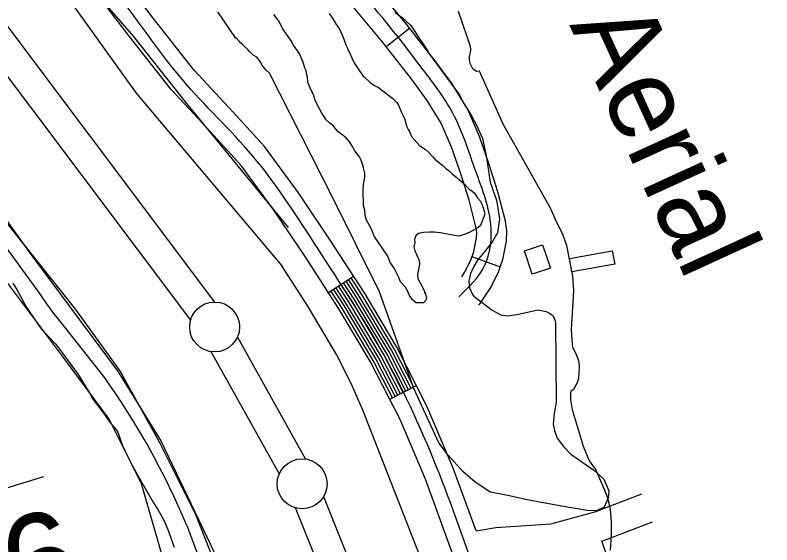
# Model space of a CAD drawing. Extents: x 3161564 to 3199464, y 849354 to 874788.
# Drawn here: x 3175133 to 3175892, y 858796 to 859326 of the extents above; entities that cross this region are included whole.
import ezdxf

# ---------------------------------------------------------------- set-up
doc = ezdxf.new("R2010")
doc.units = 0
for name, color, linetype in [('V-BLDG-OTLN', 7, 'Continuous'), ('V-CHAN-DOCK', 7, 'Continuous'), ('V-LEVE-TOET', 7, 'Continuous'), ('V-RIVR-IDEN', 7, 'Continuous'), ('V-ROAD-CNTR', 7, 'Continuous'), ('V-SITE-VEGE', 7, 'Continuous'), ('V-SURV-IDEN', 7, 'Continuous'), ('V-SURV-LINE', 7, 'Continuous'), ('V-TOPO-SHOR', 7, 'Continuous'), ('V-WETL-SWMP', 7, 'Continuous')]:
    doc.layers.add(name, color=color, linetype=linetype)

msp = doc.modelspace()

# ---------------------------------------------------------------- linework, layer by layer
at = {"layer": 'V-BLDG-OTLN'}
msp.add_lwpolyline([(3175651.16, 859066.65), (3175643.43, 859089.98), (3175661.77, 859096.05), (3175669.5, 859072.73)], close=True, dxfattribs=at)
at = {"layer": 'V-CHAN-DOCK'}
msp.add_lwpolyline([(3175734, 859076.81), (3175690.95, 859068.94), (3175688.51, 859082.31), (3175731.56, 859090.18), (3175734, 859076.81)], dxfattribs=at)
at = {"layer": 'V-LEVE-TOET'}
for points in [[(3174822.78, 860492.26), (3174886.6, 860028.81), (3174918.62, 859791.67), (3174921.63, 859740.59), (3174927.27, 859707.25), (3174948.58, 859663.98), (3174965.53, 859636.63), (3174988.54, 859602.23), (3175016.54, 859565.42), (3175046.49, 859530.13), (3175135.41, 859413.83), (3175254.44, 859247.93), (3175400.49, 859074.96)], [(3175459.51, 858433.36), (3175350.45, 858733.64), (3175314.47, 858825.09), (3175277.8, 858898.39), (3175238.01, 858970.18), (3175193.79, 859031.23), (3175113.88, 859131.14), (3174929.13, 859366.95), (3174810.69, 859521.64), (3174784.73, 859564.98), (3174763.7, 859601.67), (3174748.49, 859640.59), (3174737.49, 859676.72), (3174726.8, 859707.83), (3174714.33, 859748.25), (3174706.34, 859779.31), (3174701.82, 859809.92), (3174688.73, 859906.02), (3174645.12, 860283.31)], [(3175729.78, 857711.99), (3175723.88, 857798.28), (3175724.56, 857978), (3175720.61, 858196.91), (3175716.66, 858263.67), (3175710.21, 858307.87), (3175700.87, 858347.53), (3175682.18, 858412.28), (3175623.64, 858568.27), (3175481.44, 858930.62), (3175470.11, 858956.73), (3175455.24, 858986.44), (3175426.26, 859034.71), (3175400.49, 859074.96)]]:
    msp.add_lwpolyline(points, dxfattribs=at)
at = {"layer": 'V-ROAD-CNTR'}
for p, q in [((3175504.78, 859294.71), (3175528.38, 859313.22)), ((3175590.9, 859084.32), (3175619.17, 859074.27)), ((3175447.08, 859048.41), (3175472.25, 859064.74)), ((3175508.56, 858941.45), (3175535.27, 858955.11))]:
    msp.add_line(p, q, dxfattribs=at)
for points in [[(3175156.53, 859461.24), (3175157.02, 859444.61), (3175160.6, 859427.15), (3175165.79, 859413.53), (3175175.94, 859396.35), (3175189.19, 859379.51), (3175217.98, 859343.85), (3175251.36, 859305.02), (3175304.75, 859237.63), (3175406.57, 859113.46)], [(3175595.21, 858809.71), (3175572.17, 858872.37), (3175546.14, 858933.84), (3175515.65, 858993.49), (3175483.12, 859047.98), (3175448.79, 859100.89), (3175416.95, 859148.17), (3175382.85, 859194.65), (3175347.15, 859233.68), (3175312.09, 859271.34), (3175271.38, 859323.19), (3175231.15, 859376.17)], [(3175588.22, 858741.77), (3175566.17, 858801.79), (3175544.27, 858861.34), (3175518.94, 858921.15), (3175489.38, 858978.96), (3175457.65, 859032.13), (3175423.76, 859084.35), (3175392.41, 859130.91), (3175359.62, 859175.59), (3175325.11, 859213.34), (3175289.27, 859251.82), (3175247.63, 859304.85), (3175207.05, 859358.3)], [(3175597.62, 859035.87), (3175599.24, 859037.39), (3175609.76, 859053.57), (3175617.36, 859069.17), (3175621.74, 859081.5), (3175625.52, 859099.77), (3175625.76, 859110.19), (3175624.45, 859120.01), (3175616.96, 859149.28), (3175607.84, 859177.72), (3175598.43, 859204.77), (3175586.74, 859231.78), (3175571.03, 859257.43), (3175553.7, 859280.93), (3175523.88, 859318.96), (3175492.81, 859356.23)], [(3175580.73, 859063.96), (3175583.6, 859068.37), (3175589.65, 859080.79), (3175592.78, 859089.6), (3175595.59, 859103.19), (3175595.71, 859108.55), (3175594.95, 859114.29), (3175588.12, 859140.98), (3175579.39, 859168.21), (3175570.46, 859193.87), (3175560.05, 859217.92), (3175546.12, 859240.67), (3175529.82, 859262.77), (3175500.55, 859300.1), (3175470.4, 859336.27)], [(3175532.6, 858953.74), (3175513.02, 858992.03), (3175480.58, 859046.4), (3175469.73, 859063.11)], [(3175519.24, 858946.92), (3175499.89, 858984.77), (3175467.84, 859038.47), (3175457.15, 859054.94)], [(3175521.91, 858948.28), (3175502.52, 858986.22), (3175470.39, 859040.06), (3175459.67, 859056.58)], [(3175524.58, 858949.65), (3175505.14, 858987.67), (3175472.93, 859041.64), (3175462.18, 859058.21)], [(3175527.25, 858951.01), (3175507.77, 858989.13), (3175475.48, 859043.23), (3175464.7, 859059.84)], [(3175529.93, 858952.38), (3175510.39, 858990.58), (3175478.03, 859044.81), (3175467.22, 859061.48)], [(3175511.23, 858942.82), (3175492.01, 858980.41), (3175460.2, 859033.71), (3175449.6, 859050.05)], [(3175513.9, 858944.18), (3175494.64, 858981.86), (3175462.75, 859035.3), (3175452.12, 859051.68)], [(3175516.57, 858945.55), (3175497.26, 858983.32), (3175465.29, 859036.88), (3175454.63, 859053.31)], [(3175173.71, 859024.73), (3175221.78, 858964.38)], [(3175595.21, 858809.71), (3175614.69, 858813.06), (3175669.83, 858816.79), (3175713.9, 858828.65), (3175761.18, 858846.86)], [(3175305.14, 858815.17), (3175483.37, 858341.71)], [(3175721.22, 858799.56), (3175723.22, 858800.09), (3175771.96, 858818.87)], [(3175766.33, 858304.14), (3175793.93, 858322.54), (3175815.16, 858384.4), (3175800.33, 858490.31), (3175779.88, 858568.69), (3175759.21, 858639.34), (3175748.35, 858719.21), (3175721.22, 858799.56)]]:
    msp.add_lwpolyline(points, dxfattribs=at)
for centre, radius, start, end in [((3169212.5, 854790.58), 7311.91, 35.385586, 39.212722), ((3174602.49, 858520.48), 761.95, 22.75237, 35.63219)]:
    msp.add_arc(centre, radius, start, end, dxfattribs=at)
for points in [[(3176879.13, 855651.91), (3176902.29, 855659.09), (3176934.11, 855667), (3176983.45, 855657.71), (3177040.65, 855639.06), (3177110.48, 855613.55), (3177170.58, 855601.76), (3177236.78, 855586.88), (3177274.78, 855573.53), (3177317.45, 855579.76), (3177362.6, 855595.69), (3177411.95, 855643.14), (3177451.73, 855679.19), (3177476.66, 855705.79), (3177478.27, 855736.95), (3177464.17, 855782.28), (3177430.75, 855833.4), (3177372.99, 855887.77), (3177287.84, 855954.83), (3177219.82, 855998.44), (3177152.98, 856039.39), (3177089.34, 856079.24), (3177023.39, 856134.32), (3176966.63, 856207.93), (3176895.25, 856290.08), (3176782.25, 856425.12), (3176693.16, 856545.3), (3176615.17, 856622.65), (3176543.92, 856726.5), (3176474.39, 856784.21), (3176414.35, 856823.58), (3176395.9, 856827.98), (3176350.82, 856806.18), (3176279.15, 856754.7), (3176211.55, 856707.42), (3176172.25, 856696.11), (3176141.13, 856702.01), (3176111.75, 856719.58), (3176032.57, 856777.37), (3175933.58, 856857.43), (3175839.01, 856930.26), (3175807.14, 856951.51), (3175770.09, 856958.67), (3175787.12, 856991.4), (3175795.09, 857040.68), (3175799.48, 857113.73), (3175810.82, 857206.92), (3175813.71, 857287.37), (3175807.75, 857386.83), (3175805.68, 857497.94), (3175801.94, 857543.61), (3175783.46, 857620.53), (3175760.24, 857716.11), (3175755.33, 857765.52), (3175754.53, 857815.64), (3175751.69, 857884.28), (3175756.31, 858015.46), (3175754.85, 858158.56), (3175753.05, 858270.8), (3175748.6, 858321.65), (3175736.5, 858372), (3175677.16, 858555.53), (3175602.24, 858747.09), (3175558.22, 858866.86), (3175502.52, 858986.22), (3175436.28, 859092.62), (3175371.24, 859185.12), (3175300.68, 859261.58), (3175219.1, 859367.23), (3175166.22, 859443.65), (3175175.33, 859507.13), (3175222, 859537.88), (3175285.34, 859568.35), (3175321.17, 859607.46), (3175310.3, 859667.21), (3175262.41, 859798.62), (3175224.64, 859877.87), (3175174.73, 859982.04), (3175144.84, 860115.36), (3175122.61, 860284.79), (3175088.43, 860568.57), (3175086.28, 860704.54), (3175072.2, 860854.52), (3175052.53, 860999.93), (3175047.5, 861166.8), (3175053.18, 861343.73), (3175066.7, 861550.38), (3175065.46, 861662.49), (3175040.18, 861767.75), (3175017.84, 861884.16), (3175008.36, 862033.9), (3174979.61, 862160.28), (3174952.14, 862274.65), (3174921.63, 862422.82), (3174896.96, 862525.55), (3174861.75, 862663.22), (3174841.1, 862738.01)], [(3175577.72, 859044.16), (3175603.5, 859074.98), (3175609.7, 859117.15), (3175593.62, 859172.97), (3175573.39, 859224.85), (3175541.76, 859271.85), (3175481.6, 859346.25), (3175421.21, 859409.36), (3175378.69, 859466.05), (3175355.28, 859514.49), (3175340.89, 859562.15), (3175329.65, 859582.2), (3175329.16, 859582.62)]]:
    msp.add_spline(points, degree=3, dxfattribs=at)
at = {"layer": 'V-SITE-VEGE'}
for points in [[(3175513.58, 859329.28), (3175521.24, 859323.64), (3175529.74, 859315.99), (3175542.7, 859296.15), (3175546.65, 859290.26), (3175547.49, 859288.53), (3175578.24, 859246.67), (3175582.88, 859237.77), (3175590.19, 859226.13), (3175595.95, 859215.36), (3175601.41, 859202.6), (3175605.1, 859185.56), (3175609, 859158.81), (3175615.4, 859140.89), (3175618.51, 859122.15), (3175616.67, 859108.02), (3175611.44, 859099.64), (3175605.66, 859092.27), (3175601.61, 859086.73), (3175596.55, 859080.78), (3175592.78, 859074.38), (3175589.43, 859067.41), (3175587.64, 859059.71), (3175588.29, 859053.14), (3175591.38, 859046.54), (3175592.64, 859044.67), (3175611.09, 859030.64), (3175619.9, 859025.98), (3175626.46, 859025.06), (3175636.19, 859026.4), (3175656.81, 859030.93), (3175665.36, 859029.42), (3175668.49, 859027.67), (3175672.18, 859025.07), (3175674.42, 859020.05), (3175674.55, 859018.19), (3175675.37, 858938.32), (3175673.27, 858927.62), (3175672.45, 858916.63), (3175673.68, 858910.04), (3175676.47, 858902.59), (3175682.53, 858894.25), (3175690.17, 858886.32), (3175713.03, 858870.53), (3175723.23, 858861.29), (3175728.12, 858849.68), (3175727.34, 858842.83), (3175723.39, 858833.44), (3175716.36, 858829.93), (3175707.93, 858829.72), (3175698.8, 858831.23), (3175688.82, 858833.19), (3175662.29, 858837.72), (3175644.46, 858841.03), (3175628.64, 858844.89), (3175609.1, 858848.5), (3175593.91, 858858.93), (3175581.86, 858869.04), (3175567.16, 858885.47), (3175557.56, 858897.7), (3175532.63, 858952.36), (3175498.41, 859049.07), (3175450.73, 859144.52), (3175387.88, 859268.12), (3175384.64, 859271.08), (3175382.82, 859272.96), (3175381.73, 859274.84), (3175380.27, 859276.35), (3175378.84, 859279.34), (3175375.21, 859284.22), (3175371.54, 859286.13), (3175368.25, 859289.53), (3175366.44, 859291.78), (3175362.78, 859294.81), (3175360.96, 859296.7), (3175359.13, 859298.21), (3175357.67, 859300.09), (3175355.85, 859301.97), (3175354.02, 859303.49), (3175336.28, 859329.38)], [(3175130.66, 859057.73), (3175135, 859050.61), (3175143.99, 859034.14), (3175156.66, 859015.39), (3175159.57, 859011.63), (3175166.5, 859004.47), (3175173.42, 858996.93), (3175183.59, 858983.78), (3175196.27, 858966.14), (3175207.47, 858947.78), (3175211.07, 858941.41), (3175220.87, 858928.64), (3175227.76, 858918.88), (3175232.85, 858912.87), (3175236.11, 858908.36), (3175238.94, 858899.78), (3175240.72, 858895.3), (3175246.09, 858883.71), (3175250.76, 858874.73), (3175257.6, 858862.01), (3175271.66, 858837.66), (3175276, 858830.91), (3175282.13, 858820.43), (3175286.05, 858811.09), (3175292.43, 858793.18)]]:
    msp.add_lwpolyline(points, dxfattribs=at)
at = {"layer": 'V-SURV-LINE'}
for points in [[(3174959.59, 859535.41), (3175332.98, 859038.87)], [(3175309.02, 859020.83), (3174935.63, 859517.37)], [(3175355.85, 859003.74), (3175424, 858881.62)], [(3175397.79, 858867.01), (3175329.65, 858989.13)], [(3175441.99, 858843.92), (3175530.86, 858622.51)], [(3175503.03, 858611.32), (3175414.16, 858832.72)]]:
    msp.add_lwpolyline(points, dxfattribs=at)
for centre in [(3175333.01, 859013.88), (3175420.63, 858856.87)]:
    msp.add_circle(centre, 25, dxfattribs=at)
at = {"layer": 'V-TOPO-SHOR'}
for points in [[(3174710.49, 859764.82), (3174726.48, 859702.65), (3174747.79, 859654.69), (3174763.78, 859619.16), (3174779.77, 859581.85), (3174806.41, 859535.67), (3174927.21, 859370.47), (3175088.86, 859169.74), (3175149.25, 859086.25), (3175236.29, 858969.01), (3175278.93, 858899.73), (3175328.66, 858796.7), (3175358.86, 858730.98)], [(3175698.35, 858978.85), (3175695.79, 858985.91), (3175692.11, 858993.8), (3175691.64, 858996.43), (3175690.63, 859011.49), (3175693.12, 859050.09), (3175691.95, 859064.83), (3175685.85, 859095.49), (3175681.55, 859107.64), (3175675.77, 859119.31), (3175669.51, 859132.95), (3175622.18, 859216.85), (3175598.62, 859270.09), (3175595.35, 859269.63), (3175591.93, 859272.28), (3175589.04, 859277.71), (3175588.42, 859281.64), (3175588.61, 859284.75), (3175589.47, 859288.83), (3175589.66, 859291.78), (3175589.36, 859294.73), (3175577.58, 859329.86)], [(3175051.55, 859155.53), (3175181.23, 858983.22), (3175227.41, 858921.05), (3175259.39, 858857.1), (3175294.91, 858734.53), (3175364.19, 858560.44), (3175444.13, 858363.27), (3175472.55, 858267.34), (3175479.66, 858205.17), (3175483.21, 858031.09), (3175470.77, 857691.8)], [(3175729.81, 858790.2), (3175730.61, 858805.74), (3175730.71, 858817.03), (3175730.45, 858823.58), (3175729.7, 858831.11), (3175728.45, 858837.51), (3175726.7, 858843.58), (3175723.51, 858851.79), (3175714.69, 858871.67), (3175712.91, 858873.82), (3175708.23, 858880.57), (3175702.63, 858894.21), (3175691.68, 858930.97), (3175689.97, 858940.8), (3175689.87, 858947.84), (3175690.22, 858949.96), (3175693.02, 858951.74), (3175693.52, 858952.39), (3175696.68, 858958.41), (3175697.87, 858962.98), (3175698.41, 858967.89), (3175698.79, 858973.94), (3175698.35, 858978.85)], [(3174024.81, 858553.34), (3174497.33, 858745.19), (3174712.27, 858803.81), (3174831.28, 858762.95), (3175161.69, 858864.2)]]:
    msp.add_lwpolyline(points, dxfattribs=at)
at = {"layer": 'V-WETL-SWMP'}
for p, q in [((3175400.25, 859314.5), (3175400.39, 859314.5)), ((3175542.98, 859047.99), (3175543.84, 859047.99))]:
    msp.add_line(p, q, dxfattribs=at)
for points in [[(3175447.89, 859327.83), (3175451.59, 859322.42), (3175454.84, 859316.8), (3175457.45, 859313.41), (3175461.54, 859304.65), (3175464.52, 859296.36), (3175466.03, 859293.21), (3175466.67, 859291.42), (3175468.18, 859288.72), (3175470.12, 859284.23), (3175473.35, 859277.72), (3175481.83, 859265.1), (3175483.15, 859264.19), (3175489.07, 859258.52), (3175493.92, 859255.32), (3175497.24, 859253.7), (3175511.54, 859242.55), (3175515.71, 859238.69), (3175517.44, 859235.99), (3175520.44, 859228.58), (3175523.24, 859222.52), (3175524.3, 859219.38), (3175525.34, 859215.13), (3175527.07, 859211.54)], [(3175485.23, 859120.87), (3175483.97, 859125.57), (3175483.61, 859130.93), (3175482.35, 859135.63), (3175481.94, 859151.23), (3175482.26, 859157.02), (3175482.98, 859159.91), (3175483.49, 859164.13), (3175483.56, 859167.92), (3175482.09, 859173.29), (3175481.26, 859177.09), (3175479.99, 859180.9), (3175478.04, 859184.28), (3175473.46, 859190.37), (3175470.43, 859195.77), (3175468.47, 859198.92), (3175464.76, 859203.21), (3175460.36, 859206.63), (3175456.62, 859209.81), (3175452.47, 859214.56), (3175448.07, 859218.2), (3175444.78, 859221.37), (3175440.22, 859228.58), (3175436.11, 859236), (3175433.54, 859241.84), (3175432.27, 859246.09), (3175429.03, 859252.38), (3175426.9, 859258.21), (3175425.68, 859265.36), (3175424.65, 859270.28), (3175423.36, 859273.2), (3175421.68, 859279.25), (3175418.46, 859286.87), (3175416.51, 859290.25), (3175414.33, 859292.74), (3175411.5, 859297.02), (3175409.99, 859300.16), (3175403.24, 859309.41), (3175401.07, 859312.79), (3175397.62, 859319.98), (3175392.39, 859326.75)], [(3175527.07, 859211.54), (3175528.37, 859209.73), (3175530.3, 859204.8), (3175538.83, 859195.3), (3175543.9, 859192.09), (3175546.97, 859189.37), (3175551.79, 859184.39), (3175553.76, 859181.9), (3175561.67, 859175.53), (3175564.96, 859172.14), (3175567.61, 859170.53), (3175571.12, 859167.13), (3175574.86, 859164.39), (3175578.16, 859161.67), (3175582.99, 859157.35), (3175588.24, 859151.92), (3175590.66, 859150.09), (3175593.3, 859147.82), (3175596.56, 859143.09), (3175599.19, 859140.15), (3175601.13, 859136.1), (3175602.4, 859132.3), (3175603.87, 859126.7), (3175599.45, 859115.63), (3175597.19, 859113.44), (3175590.21, 859109.55), (3175585.27, 859107.18), (3175579.22, 859105.05), (3175577.66, 859104.85), (3175573.43, 859105.37), (3175559.44, 859108.28), (3175552.54, 859108.84), (3175548.76, 859108.9), (3175542.51, 859108.56), (3175537.37, 859107.53), (3175535.11, 859105.78), (3175533.49, 859101.8), (3175533.65, 859098.45), (3175532.69, 859094.24), (3175533.74, 859090.21), (3175537.83, 859081.45), (3175538.44, 859078.1), (3175538.42, 859076.76), (3175536.24, 859066.55), (3175536.62, 859062.31), (3175537.06, 859061.85), (3175541.59, 859053.09), (3175543.31, 859049.27), (3175544.81, 859045.68), (3175545.19, 859041.89), (3175544.95, 859041), (3175542.45, 859037.92), (3175535.1, 859038.04), (3175531.14, 859041.23), (3175528.32, 859045.51), (3175526.39, 859050.22), (3175524.22, 859053.6), (3175519.19, 859059.25), (3175517.47, 859063.29), (3175512.95, 859072.73), (3175509.03, 859078.36), (3175506.46, 859084.65), (3175492.76, 859104.93), (3175490.84, 859110.08), (3175489.12, 859113.9), (3175485.23, 859120.87)]]:
    msp.add_lwpolyline(points, dxfattribs=at)

# ---------------------------------------------------------------- texts
at = {"layer": 'V-RIVR-IDEN'}
msp.add_text('Aerial', height=83, rotation=294.56708, dxfattribs=at).set_placement((3175688.34, 859316.51))
at = {"layer": 'V-SURV-IDEN'}
msp.add_text('716+36.6', height=100, rotation=18.27823, dxfattribs=at).set_placement((3174677.43, 858565.35))

doc.saveas('drawing.dxf')
